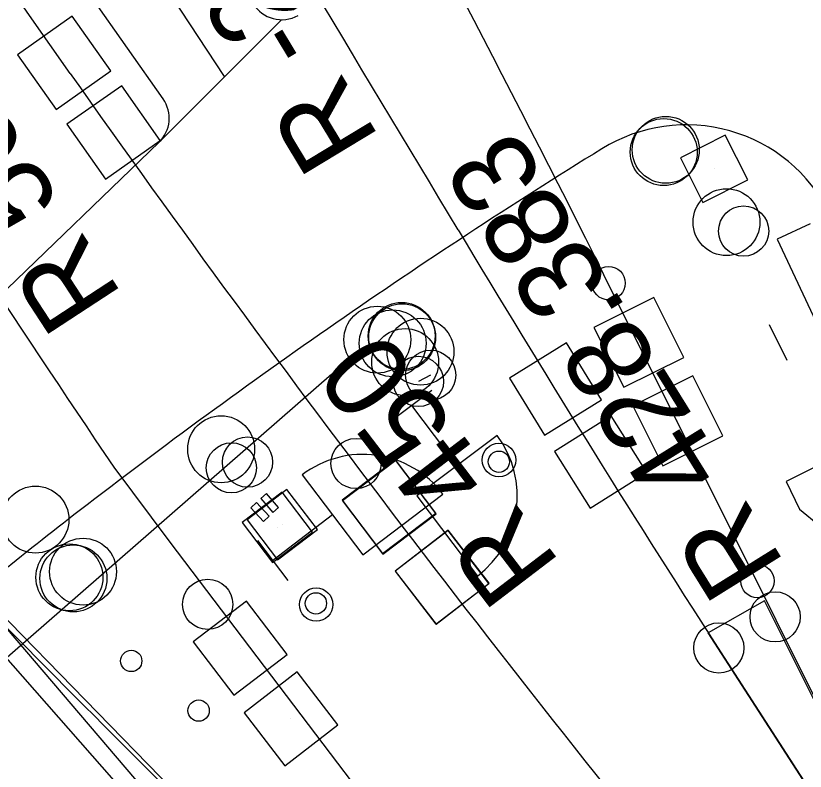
# Model space of a CAD drawing. Extents: x 1596643 to 1597288, y 13057194 to 13057957.
# Drawn here: x 1596885.06 to 1596908.65, y 13057483.67 to 13057506.23 of the extents above; entities that cross this region are included whole.
import ezdxf

# ---------------------------------------------------------------- set-up
doc = ezdxf.new("R2010")
doc.units = 0
for name, color, linetype in [('A Isolerskarv P', 7, 'Continuous'), ('A Spårgeometri T', 7, 'Continuous'), ('A spårmitt L', 7, 'Continuous'), ('B bks1 P', 7, 'Continuous'), ('B bks2 P', 7, 'Continuous'), ('B kabelbrunn mindre än 150 cm NK P', 7, 'Continuous'), ('B kabelbrunn större än 150 cm L', 7, 'Continuous'), ('B kabelränna större än 500 mm NK L', 7, 'Continuous'), ('B växel linjevikt 0 L', 7, 'Continuous'), ('BAS Level 15', 7, 'Continuous'), ('BAS Level 29', 7, 'Continuous'), ('C skåp L', 7, 'Continuous'), ('D Plattform L', 7, 'Continuous'), ('D Plattformsdetalj L', 7, 'Continuous'), ('E ktl sträva stag fundament L', 7, 'Continuous'), ('E ktlbrygga L', 7, 'Continuous'), ('E ktlstolpe normal centrum P', 7, 'Continuous'), ('E sträva centrum P', 7, 'Continuous'), ('F balis P', 7, 'Continuous'), ('F dvärgsignal fristående P', 7, 'Continuous'), ('F signal fristående P', 7, 'Continuous'), ('F vägskyddsanordning stolpe driv P', 7, 'Continuous')]:
    doc.layers.add(name, color=color, linetype=linetype)

msp = doc.modelspace()

# ---------------------------------------------------------------- linework, layer by layer
at = {"layer": 'A Isolerskarv P'}
for centre in [(1596895.225, 13057492.862), (1596895.225, 13057492.862), (1596890.793, 13057488.656), (1596890.793, 13057488.656)]:
    msp.add_circle(centre, 0.75, dxfattribs=at)
at = {"layer": 'A spårmitt L'}
for points in [[(1596886.686, 13057504.512), (1596885.471, 13057506.242), (1596884.265, 13057507.977), (1596883.065, 13057509.717), (1596881.872, 13057511.462), (1596880.686, 13057513.212), (1596879.507, 13057514.966), (1596878.333, 13057516.723), (1596877.164, 13057518.484), (1596876, 13057520.249), (1596874.841, 13057522.016), (1596873.686, 13057523.786), (1596872.535, 13057525.559), (1596871.387, 13057527.334), (1596870.242, 13057529.11), (1596869.099, 13057530.889), (1596867.959, 13057532.668), (1596866.82, 13057534.449), (1596865.683, 13057536.23), (1596864.546, 13057538.012), (1596863.41, 13057539.794), (1596846.221, 13057566.757)], [(1596861.603, 13057516.009), (1596866.442, 13057509.391), (1596878.849, 13057493.781), (1596895.097, 13057475.302), (1596900.34, 13057469.714), (1596931.231, 13057437.468), (1596933.8, 13057434.835)], [(1596915.51, 13057472.702), (1596902.636, 13057498.496)], [(1596887.988, 13057492.75), (1596889.66, 13057490.516), (1596900.094, 13057476.776), (1596906.53, 13057469.464), (1596928.328, 13057446.663), (1596936.899, 13057437.942), (1596957.336, 13057417.351), (1597001.928, 13057371.989), (1597034.879, 13057338.506), (1597063.764, 13057309.15)], [(1596906.028, 13057487.38), (1596921.777, 13057463.002), (1596931.207, 13057448.128)]]:
    msp.add_lwpolyline(points, dxfattribs=at)
for centre, radius, start, end in [((1596499.999, 13057297.54), 450, 26.52378, 31.49284), ((1595182.157, 13056472.741), 2000, 30.900492, 31.412375), ((1597302.22, 13057772.77), 500, 212.24025, 214.05857), ((1597254.361, 13057763.969), 450.004, 215.20947, 219.47575), ((1597265.857, 13057719.834), 428.383, 210.90049, 212.86295), ((1597083.054, 13057678.855), 279.382, 221.11205, 225.426)]:
    msp.add_arc(centre, radius, start, end, dxfattribs=at)
msp.add_spline([(1596921.486, 13057453.819), (1596905.281, 13057468.17), (1596896.354, 13057476.52), (1596877.996, 13057494.854)], degree=3, dxfattribs=at)
at = {"layer": 'B bks1 P'}
msp.add_circle((1596907.75, 13057488.281), 0.75, dxfattribs=at)
msp.add_circle((1596907.75, 13057488.281), 0.75, dxfattribs=at)
at = {"layer": 'B bks2 P'}
msp.add_circle((1596906.068, 13057487.354), 0.75, dxfattribs=at)
msp.add_circle((1596906.068, 13057487.354), 0.75, dxfattribs=at)
at = {"layer": 'B kabelbrunn mindre än 150 cm NK P'}
for centre in [(1596899.498, 13057492.967), (1596899.498, 13057492.967), (1596894.034, 13057488.649), (1596894.034, 13057488.649)]:
    msp.add_circle(centre, 0.5, dxfattribs=at)
at = {"layer": 'B kabelbrunn större än 150 cm L'}
msp.add_lwpolyline([(1596910.036, 13057493.303), (1596908.083, 13057492.328), (1596908.484, 13057491.494), (1596909.693, 13057490.505), (1596911.075, 13057491.186), (1596910.036, 13057493.303)], dxfattribs=at)
at = {"layer": 'B kabelränna större än 500 mm NK L'}
msp.add_lwpolyline([(1596908.8, 13057500.022), (1596907.816, 13057499.56), (1596912.644, 13057489.282)], dxfattribs=at)
at = {"layer": 'B växel linjevikt 0 L'}
for p, q in [((1596882.884, 13057490.154), (1596901.664, 13057468.173)), ((1596882.884, 13057490.154), (1596903.084, 13057469.471)), ((1596882.884, 13057490.154), (1596901.664, 13057468.173)), ((1596882.884, 13057490.154), (1596903.084, 13057469.471)), ((1596907.433, 13057488.762), (1596905.754, 13057487.804)), ((1596907.433, 13057488.762), (1596905.754, 13057487.804)), ((1596915.236, 13057473.125), (1596907.433, 13057488.762)), ((1596915.236, 13057473.125), (1596907.433, 13057488.762)), ((1596915.236, 13057473.125), (1596905.754, 13057487.804)), ((1596915.236, 13057473.125), (1596905.754, 13057487.804))]:
    msp.add_line(p, q, dxfattribs=at)
at = {"layer": 'BAS Level 15'}
for centre in [(1596902.773, 13057498.249), (1596902.773, 13057498.249), (1596907.222, 13057489.354), (1596907.222, 13057489.354)]:
    msp.add_circle(centre, 0.5, dxfattribs=at)
at = {"layer": 'BAS Level 29'}
for centre in [(1596899.494, 13057492.916), (1596899.494, 13057492.916), (1596894.025, 13057488.685), (1596894.025, 13057488.685), (1596888.507, 13057486.966), (1596888.507, 13057486.966), (1596890.521, 13057485.482), (1596890.521, 13057485.482)]:
    msp.add_circle(centre, 0.318, dxfattribs=at)
at = {"layer": 'C skåp L'}
msp.add_line((1596908.11, 13057495.938), (1596907.58, 13057497.007), dxfattribs=at)
at = {"layer": 'D Plattform L'}
for p, q in [((1596891.297, 13057504.419), (1596888.111, 13057509.274)), ((1596889.462, 13057503.75), (1596886.428, 13057508.08)), ((1596892.993, 13057506.119), (1596889.337, 13057502.456)), ((1596884.112, 13057497.423), (1596889.337, 13057502.456))]:
    msp.add_line(p, q, dxfattribs=at)
for centre, radius, start, end in [((1596893.003, 13057507.119), 1, 211.3106, 299.3796), ((1596888.643, 13057503.176), 1, 313.9263, 35.0282), ((1596905.094, 13057498.178), 4.8, 26.7967, 121.7161), ((1596997.759, 13057348.235), 181.066, 121.71603, 124.72307), ((1597001.429, 13057342.939), 187.509, 124.72308, 127.62679), ((1596959.547, 13057397.271), 118.908, 127.62678, 130.70537)]:
    msp.add_arc(centre, radius, start, end, dxfattribs=at)
at = {"layer": 'D Plattformsdetalj L'}
for points in [[(1596892.376, 13057491.822), (1596892.736, 13057491.399), (1596892.911, 13057491.548), (1596892.552, 13057491.971), (1596892.376, 13057491.822)], [(1596892.085, 13057491.538), (1596892.461, 13057491.134), (1596892.63, 13057491.291), (1596892.254, 13057491.694), (1596892.085, 13057491.538)]]:
    msp.add_lwpolyline(points, dxfattribs=at)
at = {"layer": 'E ktl sträva stag fundament L'}
msp.add_line((1596897.455, 13057495.501), (1596897.09, 13057495.314), dxfattribs=at)
at = {"layer": 'E ktlbrygga L'}
msp.add_lwpolyline([(1596894.502, 13057495.528), (1596880.1, 13057482.978)], dxfattribs=at)
at = {"layer": 'E ktlstolpe normal centrum P'}
for centre in [(1596906.808, 13057499.805), (1596906.808, 13057499.805), (1596897.455, 13057495.501), (1596897.455, 13057495.501), (1596897.09, 13057495.314), (1596897.09, 13057495.314), (1596891.501, 13057492.733), (1596891.501, 13057492.733), (1596891.983, 13057492.905), (1596891.983, 13057492.905)]:
    msp.add_circle(centre, 0.75, dxfattribs=at)
at = {"layer": 'E sträva centrum P'}
for p, q in [((1596906.258, 13057502.671), (1596904.918, 13057501.997)), ((1596906.258, 13057502.671), (1596904.918, 13057501.997)), ((1596906.932, 13057501.331), (1596906.258, 13057502.671)), ((1596906.932, 13057501.331), (1596906.258, 13057502.671)), ((1596904.918, 13057501.997), (1596905.592, 13057500.657)), ((1596904.918, 13057501.997), (1596905.592, 13057500.657)), ((1596905.925, 13057501.664), (1596905.925, 13057501.664)), ((1596905.925, 13057501.664), (1596905.925, 13057501.664)), ((1596905.592, 13057500.657), (1596906.932, 13057501.331)), ((1596905.592, 13057500.657), (1596906.932, 13057501.331)), ((1596893.162, 13057492.084), (1596891.968, 13057491.176)), ((1596893.162, 13057492.084), (1596891.968, 13057491.176)), ((1596894.07, 13057490.89), (1596893.162, 13057492.084)), ((1596894.07, 13057490.89), (1596893.162, 13057492.084)), ((1596893.014, 13057492.003), (1596891.821, 13057491.096)), ((1596893.014, 13057492.003), (1596891.821, 13057491.096)), ((1596893.921, 13057490.81), (1596893.014, 13057492.003)), ((1596893.921, 13057490.81), (1596893.014, 13057492.003)), ((1596891.968, 13057491.176), (1596892.876, 13057489.982)), ((1596891.968, 13057491.176), (1596892.876, 13057489.982)), ((1596891.821, 13057491.096), (1596892.728, 13057489.903)), ((1596891.821, 13057491.096), (1596892.728, 13057489.903)), ((1596892.871, 13057490.953), (1596892.871, 13057490.953)), ((1596892.871, 13057490.953), (1596892.871, 13057490.953)), ((1596892.876, 13057489.982), (1596894.07, 13057490.89)), ((1596892.876, 13057489.982), (1596894.07, 13057490.89)), ((1596893.019, 13057491.033), (1596893.019, 13057491.033)), ((1596893.019, 13057491.033), (1596893.019, 13057491.033)), ((1596892.728, 13057489.903), (1596893.921, 13057490.81)), ((1596892.728, 13057489.903), (1596893.921, 13057490.81))]:
    msp.add_line(p, q, dxfattribs=at)
at = {"layer": 'F balis P'}
for p, q in [((1596886.746, 13057506.223), (1596885.11, 13057505.073)), ((1596886.746, 13057506.223), (1596885.11, 13057505.073)), ((1596887.896, 13057504.587), (1596886.746, 13057506.223)), ((1596887.896, 13057504.587), (1596886.746, 13057506.223)), ((1596885.11, 13057505.073), (1596886.26, 13057503.437)), ((1596885.11, 13057505.073), (1596886.26, 13057503.437)), ((1596886.503, 13057504.83), (1596886.503, 13057504.83)), ((1596886.503, 13057504.83), (1596886.503, 13057504.83)), ((1596886.26, 13057503.437), (1596887.896, 13057504.587)), ((1596886.26, 13057503.437), (1596887.896, 13057504.587)), ((1596888.223, 13057504.143), (1596886.586, 13057502.994)), ((1596888.223, 13057504.143), (1596886.586, 13057502.994)), ((1596889.372, 13057502.506), (1596888.223, 13057504.143)), ((1596889.372, 13057502.506), (1596888.223, 13057504.143)), ((1596886.586, 13057502.994), (1596887.735, 13057501.357)), ((1596886.586, 13057502.994), (1596887.735, 13057501.357)), ((1596887.979, 13057502.75), (1596887.979, 13057502.75)), ((1596887.979, 13057502.75), (1596887.979, 13057502.75)), ((1596887.735, 13057501.357), (1596889.372, 13057502.506)), ((1596887.735, 13057501.357), (1596889.372, 13057502.506)), ((1596904.125, 13057497.821), (1596902.336, 13057496.928)), ((1596904.125, 13057497.821), (1596902.336, 13057496.928)), ((1596905.018, 13057496.032), (1596904.125, 13057497.821)), ((1596905.018, 13057496.032), (1596904.125, 13057497.821)), ((1596902.336, 13057496.928), (1596903.229, 13057495.139)), ((1596902.336, 13057496.928), (1596903.229, 13057495.139)), ((1596901.515, 13057496.463), (1596899.812, 13057495.414)), ((1596901.515, 13057496.463), (1596899.812, 13057495.414)), ((1596902.564, 13057494.76), (1596901.515, 13057496.463)), ((1596902.564, 13057494.76), (1596901.515, 13057496.463)), ((1596903.677, 13057496.48), (1596903.677, 13057496.48)), ((1596903.677, 13057496.48), (1596903.677, 13057496.48)), ((1596903.229, 13057495.139), (1596905.018, 13057496.032)), ((1596903.229, 13057495.139), (1596905.018, 13057496.032)), ((1596899.812, 13057495.414), (1596900.861, 13057493.711)), ((1596899.812, 13057495.414), (1596900.861, 13057493.711)), ((1596905.292, 13057495.478), (1596903.503, 13057494.585)), ((1596905.292, 13057495.478), (1596903.503, 13057494.585)), ((1596906.185, 13057493.689), (1596905.292, 13057495.478)), ((1596906.185, 13057493.689), (1596905.292, 13057495.478)), ((1596901.188, 13057495.087), (1596901.188, 13057495.087)), ((1596901.188, 13057495.087), (1596901.188, 13057495.087)), ((1596900.861, 13057493.711), (1596902.564, 13057494.76)), ((1596900.861, 13057493.711), (1596902.564, 13057494.76)), ((1596903.503, 13057494.585), (1596904.396, 13057492.796)), ((1596903.503, 13057494.585), (1596904.396, 13057492.796)), ((1596902.855, 13057494.285), (1596901.159, 13057493.225)), ((1596902.855, 13057494.285), (1596901.159, 13057493.225)), ((1596903.915, 13057492.589), (1596902.855, 13057494.285)), ((1596903.915, 13057492.589), (1596902.855, 13057494.285)), ((1596904.844, 13057494.137), (1596904.844, 13057494.137)), ((1596904.844, 13057494.137), (1596904.844, 13057494.137)), ((1596904.396, 13057492.796), (1596906.185, 13057493.689)), ((1596904.396, 13057492.796), (1596906.185, 13057493.689)), ((1596901.159, 13057493.225), (1596902.219, 13057491.529)), ((1596901.159, 13057493.225), (1596902.219, 13057491.529)), ((1596896.402, 13057492.976), (1596894.81, 13057491.766)), ((1596896.402, 13057492.976), (1596894.81, 13057491.766)), ((1596896.41, 13057492.953), (1596894.818, 13057491.743)), ((1596896.41, 13057492.953), (1596894.818, 13057491.743)), ((1596897.612, 13057491.384), (1596896.402, 13057492.976)), ((1596897.612, 13057491.384), (1596896.402, 13057492.976)), ((1596897.62, 13057491.361), (1596896.41, 13057492.953)), ((1596897.62, 13057491.361), (1596896.41, 13057492.953)), ((1596902.537, 13057492.907), (1596902.537, 13057492.907)), ((1596902.537, 13057492.907), (1596902.537, 13057492.907)), ((1596902.219, 13057491.529), (1596903.915, 13057492.589)), ((1596902.219, 13057491.529), (1596903.915, 13057492.589)), ((1596894.81, 13057491.766), (1596896.02, 13057490.174)), ((1596894.81, 13057491.766), (1596896.02, 13057490.174)), ((1596894.818, 13057491.743), (1596896.028, 13057490.151)), ((1596894.818, 13057491.743), (1596896.028, 13057490.151)), ((1596896.02, 13057490.174), (1596897.612, 13057491.384)), ((1596896.02, 13057490.174), (1596897.612, 13057491.384)), ((1596896.028, 13057490.151), (1596897.62, 13057491.361)), ((1596896.028, 13057490.151), (1596897.62, 13057491.361)), ((1596896.211, 13057491.575), (1596896.211, 13057491.575)), ((1596896.211, 13057491.575), (1596896.211, 13057491.575)), ((1596896.219, 13057491.552), (1596896.219, 13057491.552)), ((1596896.219, 13057491.552), (1596896.219, 13057491.552)), ((1596897.977, 13057490.863), (1596896.393, 13057489.643)), ((1596897.977, 13057490.863), (1596896.393, 13057489.643)), ((1596897.983, 13057490.871), (1596896.399, 13057489.651)), ((1596897.983, 13057490.871), (1596896.399, 13057489.651)), ((1596899.197, 13057489.279), (1596897.977, 13057490.863)), ((1596899.197, 13057489.279), (1596897.977, 13057490.863)), ((1596899.203, 13057489.287), (1596897.983, 13057490.871)), ((1596899.203, 13057489.287), (1596897.983, 13057490.871)), ((1596896.393, 13057489.643), (1596897.613, 13057488.059)), ((1596896.393, 13057489.643), (1596897.613, 13057488.059)), ((1596896.399, 13057489.651), (1596897.619, 13057488.067)), ((1596896.399, 13057489.651), (1596897.619, 13057488.067)), ((1596897.801, 13057489.469), (1596897.801, 13057489.469)), ((1596897.801, 13057489.469), (1596897.801, 13057489.469)), ((1596897.613, 13057488.059), (1596899.197, 13057489.279)), ((1596897.613, 13057488.059), (1596899.197, 13057489.279)), ((1596897.619, 13057488.067), (1596899.203, 13057489.287)), ((1596897.619, 13057488.067), (1596899.203, 13057489.287)), ((1596897.795, 13057489.461), (1596897.795, 13057489.461)), ((1596897.795, 13057489.461), (1596897.795, 13057489.461)), ((1596891.955, 13057488.747), (1596890.361, 13057487.537)), ((1596891.955, 13057488.747), (1596890.361, 13057487.537)), ((1596893.165, 13057487.153), (1596891.955, 13057488.747)), ((1596893.165, 13057487.153), (1596891.955, 13057488.747)), ((1596890.361, 13057487.537), (1596891.571, 13057485.943)), ((1596890.361, 13057487.537), (1596891.571, 13057485.943)), ((1596891.763, 13057487.345), (1596891.763, 13057487.345)), ((1596891.763, 13057487.345), (1596891.763, 13057487.345)), ((1596891.571, 13057485.943), (1596893.165, 13057487.153)), ((1596891.571, 13057485.943), (1596893.165, 13057487.153)), ((1596893.462, 13057486.639), (1596891.878, 13057485.417)), ((1596893.462, 13057486.639), (1596891.878, 13057485.417)), ((1596894.684, 13057485.055), (1596893.462, 13057486.639)), ((1596894.684, 13057485.055), (1596893.462, 13057486.639)), ((1596891.878, 13057485.417), (1596893.1, 13057483.833)), ((1596891.878, 13057485.417), (1596893.1, 13057483.833)), ((1596893.281, 13057485.236), (1596893.281, 13057485.236)), ((1596893.281, 13057485.236), (1596893.281, 13057485.236)), ((1596893.1, 13057483.833), (1596894.684, 13057485.055)), ((1596893.1, 13057483.833), (1596894.684, 13057485.055))]:
    msp.add_line(p, q, dxfattribs=at)
at = {"layer": 'F dvärgsignal fristående P'}
for p, q in [((1596897.489, 13057495.047), (1596896.291, 13057494.145)), ((1596897.489, 13057495.047), (1596896.291, 13057494.145)), ((1596898.244, 13057492.799), (1596896.89, 13057494.596)), ((1596898.244, 13057492.799), (1596896.89, 13057494.596)), ((1596894.526, 13057491.33), (1596892.734, 13057489.969)), ((1596894.526, 13057491.33), (1596892.734, 13057489.969)), ((1596892.28, 13057490.567), (1596893.188, 13057489.371)), ((1596892.28, 13057490.567), (1596893.188, 13057489.371))]:
    msp.add_line(p, q, dxfattribs=at)
for points in [[(1596899.442, 13057493.702), (1596897.046, 13057491.896), (1596898.852, 13057489.5)], [(1596899.442, 13057493.702), (1596897.046, 13057491.896), (1596898.852, 13057489.5)], [(1596893.618, 13057492.524), (1596895.433, 13057490.135), (1596897.822, 13057491.95)], [(1596893.618, 13057492.524), (1596895.433, 13057490.135), (1596897.822, 13057491.95)]]:
    msp.add_lwpolyline(points, dxfattribs=at)
for centre, start, end in [((1596897.046, 13057491.896), 307, 37), ((1596897.046, 13057491.896), 307, 37), ((1596895.433, 13057490.135), 37.2129, 127.2129), ((1596895.433, 13057490.135), 37.2129, 127.2129)]:
    msp.add_arc(centre, 3, start, end, dxfattribs=at)
at = {"layer": 'F signal fristående P'}
for centre in [(1596904.421, 13057502.165), (1596904.421, 13057502.165), (1596906.297, 13057500.071), (1596906.297, 13057500.071), (1596895.862, 13057496.562), (1596895.862, 13057496.562), (1596896.589, 13057496.673), (1596896.589, 13057496.673), (1596897.152, 13057496.203), (1596897.152, 13057496.203), (1596896.693, 13057495.892), (1596896.693, 13057495.892), (1596891.194, 13057493.288), (1596891.194, 13057493.288), (1596885.645, 13057491.187), (1596885.645, 13057491.187), (1596886.659, 13057489.463), (1596886.659, 13057489.463)]:
    msp.add_circle(centre, 1, dxfattribs=at)
at = {"layer": 'F vägskyddsanordning stolpe driv P'}
for centre in [(1596904.481, 13057502.231), (1596904.481, 13057502.231), (1596896.604, 13057496.634), (1596896.604, 13057496.634), (1596896.32, 13057496.452), (1596896.32, 13057496.452), (1596886.778, 13057489.431), (1596886.778, 13057489.431), (1596887.066, 13057489.632), (1596887.066, 13057489.632)]:
    msp.add_circle(centre, 1, dxfattribs=at)

# ---------------------------------------------------------------- texts
at = {"layer": 'A Spårgeometri T'}
for s, height, rotation, p in [('R -2000', 2.5, 121.158, (1596895.954, 13057502.562)), ('R 500', 2.499, 123.156, (1596888.271, 13057497.871)), ('R 428.383', 2.5, 121.887, (1596908.066, 13057489.853)), ('R 450', 2.499, 127.35, (1596901.369, 13057489.866))]:
    msp.add_text(s, height=height, rotation=rotation, dxfattribs=at).set_placement(p)

doc.saveas('drawing.dxf')
